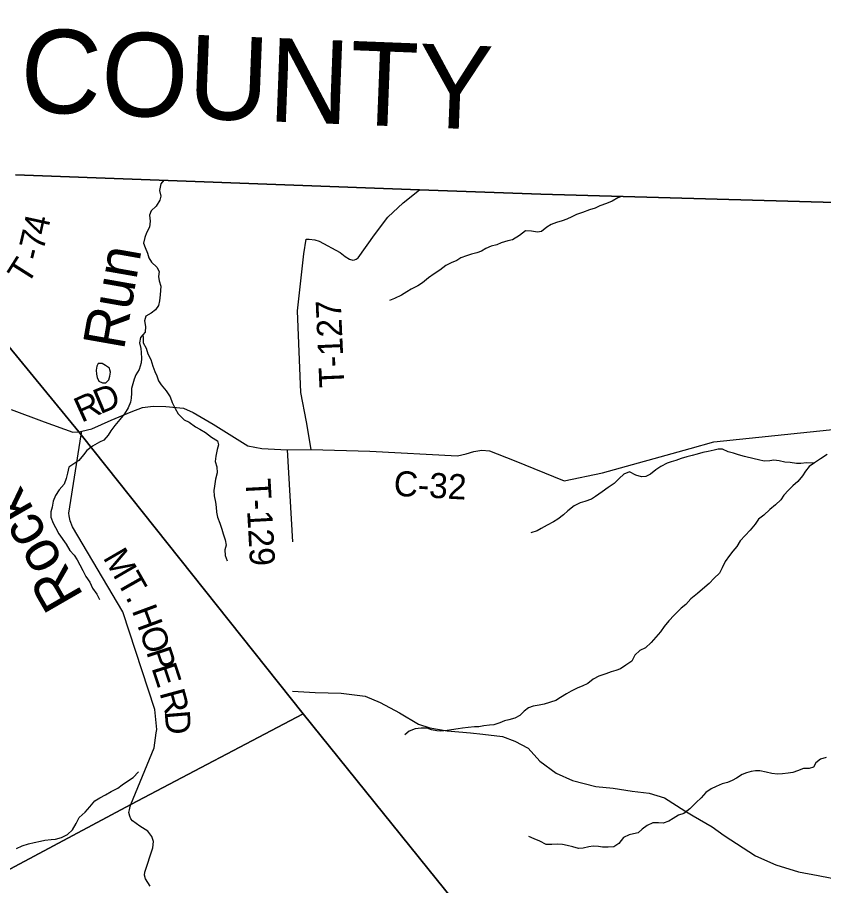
# Model space of a CAD drawing. Extents: x 1624196 to 2029251, y 146837 to 440034.
# Drawn here: x 1777616 to 1787257, y 341386 to 351773 of the extents above; entities that cross this region are included whole.
import ezdxf

# ---------------------------------------------------------------- set-up
doc = ezdxf.new("R2010")
doc.units = 0
for name, color, linetype in [('GM_X_Adjacent_County', 7, 'Continuous'), ('GM_X_Adjacent_County_Text', 7, 'Continuous'), ('GM_X_County', 7, 'Continuous'), ('GM_X_County_Road', 7, 'Continuous'), ('GM_X_County_Road_Text', 7, 'Continuous'), ('GM_X_Minor_Lake', 7, 'Continuous'), ('GM_X_Minor_River', 7, 'Continuous'), ('GM_X_Minor_River_Text', 7, 'Continuous'), ('GM_X_Township', 7, 'Continuous'), ('GM_X_Township_Road', 7, 'Continuous'), ('GM_X_Township_Road_Text', 7, 'Continuous'), ('GM_X_Township_ROW', 7, 'Continuous')]:
    doc.layers.add(name, color=color, linetype=linetype)

msp = doc.modelspace()

# ---------------------------------------------------------------- linework, layer by layer
at = {"layer": 'GM_X_Adjacent_County'}
msp.add_lwpolyline([(1826336, 348649), (1819510, 348957), (1818598, 348960), (1813935, 349079), (1813587, 349087), (1795056, 349285), (1795014, 349286), (1790774, 349462), (1789921, 349486), (1783877, 349656), (1782423, 349710), (1777594, 349890)], dxfattribs=at)
at = {"layer": 'GM_X_County'}
msp.add_lwpolyline([(1777594, 349890), (1782423, 349710), (1783877, 349656), (1789921, 349486), (1790774, 349462), (1795014, 349286), (1795056, 349285), (1813587, 349087), (1813935, 349079), (1818598, 348960), (1819510, 348957), (1826336, 348649)], dxfattribs=at)
at = {"layer": 'GM_X_County_Road'}
for points in [[(1777542, 347083), (1777938, 346934), (1778279, 346810), (1778350, 346813), (1778385, 346821)], [(1778385, 346821), (1778508, 346852), (1778739, 346954), (1778975, 347055), (1779110, 347107), (1779238, 347120), (1779391, 347118), (1779603, 347096), (1779718, 347046), (1779958, 346906), (1780370, 346648), (1780537, 346614), (1780843, 346601), (1781128, 346602), (1781831, 346584), (1782878, 346528), (1782984, 346551), (1783072, 346578), (1783170, 346597), (1783262, 346588), (1783558, 346473), (1784156, 346229), (1784612, 346325), (1785661, 346615), (1785944, 346695), (1787517, 346859)], [(1779280, 343233), (1779283, 343254), (1779258, 343492), (1778876, 344660), (1778275, 345680), (1778246, 345749), (1778235, 345810), (1778231, 345842), (1778378, 346777), (1778385, 346821)], [(1779202, 341378), (1779149, 341468), (1779137, 341510), (1779138, 341548), (1779237, 341840), (1779242, 341914), (1779223, 341974), (1779176, 342038), (1779079, 342097), (1778991, 342160), (1778972, 342185), (1778960, 342216), (1778950, 342261), (1778956, 342294), (1778965, 342332), (1778974, 342355), (1779253, 343033), (1779277, 343213), (1779280, 343233)]]:
    msp.add_lwpolyline(points, dxfattribs=at)
at = {"layer": 'GM_X_Minor_Lake'}
for points in [[(1778723, 347556), (1778717, 347575), (1778671, 347607), (1778629, 347632), (1778583, 347630), (1778565, 347599), (1778556, 347552), (1778562, 347506), (1778571, 347464)], [(1778571, 347464), (1778591, 347422), (1778633, 347399), (1778675, 347401), (1778711, 347438), (1778722, 347482), (1778730, 347528), (1778723, 347556)]]:
    msp.add_lwpolyline(points, dxfattribs=at)
at = {"layer": 'GM_X_Minor_River'}
for points in [[(1779369, 349825), (1779331, 349782), (1779316, 349702), (1779331, 349635), (1779321, 349585), (1779274, 349515), (1779215, 349460), (1779196, 349406), (1779202, 349334), (1779195, 349262), (1779160, 349194), (1779139, 349140), (1779122, 349070), (1779142, 349019), (1779171, 348951), (1779188, 348896), (1779220, 348846), (1779285, 348785), (1779311, 348734), (1779304, 348674), (1779313, 348620), (1779333, 348557), (1779326, 348505), (1779324, 348455), (1779317, 348381), (1779302, 348327), (1779267, 348273), (1779215, 348234), (1779150, 348198), (1779135, 348144), (1779149, 348076), (1779144, 348008), (1779087, 347944), (1779078, 347878), (1779091, 347812), (1779097, 347762), (1779100, 347693), (1779095, 347641), (1779072, 347561), (1779034, 347495), (1779013, 347444), (1778996, 347390), (1778982, 347332), (1778981, 347279), (1778978, 347219), (1778970, 347169), (1778939, 347101), (1778896, 347028), (1778839, 346962), (1778782, 346892), (1778735, 346825), (1778700, 346773), (1778650, 346715), (1778597, 346692), (1778514, 346645), (1778448, 346591), (1778407, 346538), (1778352, 346472), (1778289, 346433), (1778231, 346391), (1778216, 346319), (1778201, 346255), (1778176, 346187), (1778115, 346120), (1778072, 346052), (1778043, 345986), (1778031, 345912), (1778014, 345858), (1778015, 345792), (1778042, 345723), (1778070, 345671), (1778111, 345596), (1778200, 345469), (1778245, 345396), (1778295, 345341), (1778330, 345285), (1778363, 345222), (1778399, 345155), (1778436, 345085), (1778481, 345018), (1778516, 344943), (1778566, 344874), (1778597, 344810)], [(1784838, 349630), (1784797, 349612), (1784729, 349573), (1784660, 349545), (1784582, 349518), (1784523, 349489), (1784457, 349471), (1784372, 349440), (1784302, 349413), (1784245, 349388), (1784185, 349358), (1784130, 349339), (1784062, 349318), (1783998, 349294), (1783947, 349263), (1783884, 349211), (1783834, 349202), (1783764, 349213), (1783692, 349218), (1783621, 349162), (1783538, 349111), (1783480, 349100), (1783401, 349077), (1783349, 349053), (1783283, 349034), (1783216, 349007), (1783166, 348977), (1783109, 348956), (1783045, 348938), (1782985, 348921), (1782920, 348894), (1782870, 348866), (1782803, 348837), (1782739, 348806), (1782668, 348750), (1782599, 348705), (1782532, 348656), (1782459, 348598), (1782405, 348563), (1782324, 348522), (1782274, 348490), (1782207, 348449), (1782124, 348410), (1782064, 348384)], [(1779114, 347975), (1779119, 347944), (1779120, 347880), (1779156, 347815), (1779177, 347749), (1779212, 347680), (1779235, 347601), (1779261, 347537), (1779282, 347484), (1779302, 347426), (1779337, 347375), (1779396, 347304), (1779442, 347232), (1779467, 347167), (1779502, 347095), (1779539, 347028), (1779611, 346959), (1779669, 346932), (1779744, 346875), (1779796, 346846), (1779866, 346805), (1779937, 346752), (1780007, 346707), (1780022, 346657), (1780006, 346603), (1779987, 346525), (1779980, 346459), (1779999, 346394), (1780004, 346326), (1779986, 346250), (1779973, 346166), (1779964, 346114), (1779969, 346050), (1779986, 345975), (1779992, 345913), (1779997, 345853), (1780008, 345792), (1780035, 345720), (1780059, 345649), (1780076, 345593), (1780101, 345522), (1780111, 345458), (1780098, 345404), (1780099, 345334), (1780126, 345271)], [(1787144, 346441), (1787053, 346444), (1786985, 346437), (1786931, 346437), (1786857, 346446), (1786793, 346451), (1786725, 346468), (1786663, 346475), (1786612, 346467), (1786546, 346464), (1786476, 346479), (1786424, 346493), (1786312, 346519), (1786237, 346540), (1786179, 346558), (1786115, 346577), (1786049, 346606), (1785997, 346609), (1785947, 346597), (1785876, 346580), (1785812, 346567), (1785744, 346549), (1785685, 346530), (1785621, 346515), (1785555, 346497), (1785488, 346472), (1785434, 346455), (1785384, 346439), (1785311, 346398), (1785251, 346358), (1785186, 346309), (1785130, 346282), (1785080, 346278), (1785012, 346295), (1784936, 346334), (1784867, 346309), (1784813, 346255), (1784752, 346198), (1784679, 346148), (1784607, 346095), (1784530, 346040), (1784479, 346008), (1784401, 345981), (1784347, 345966), (1784272, 345930), (1784197, 345871), (1784147, 345823), (1784080, 345770), (1784026, 345739), (1783949, 345697), (1783880, 345658), (1783830, 345632), (1783754, 345607)], [(1787298, 346542), (1787220, 346490), (1787149, 346445), (1787082, 346398), (1787040, 346344), (1787003, 346288), (1786950, 346221), (1786887, 346167), (1786835, 346118), (1786782, 346058), (1786743, 346002), (1786681, 345941), (1786612, 345887), (1786543, 345818), (1786478, 345769), (1786439, 345709), (1786377, 345639), (1786318, 345574), (1786259, 345510), (1786218, 345443), (1786171, 345387), (1786131, 345335), (1786078, 345264), (1786043, 345188), (1786012, 345124), (1785949, 345063), (1785888, 344999), (1785808, 344934), (1785747, 344882), (1785670, 344817), (1785607, 344748), (1785553, 344704), (1785471, 344623), (1785405, 344555), (1785350, 344486), (1785305, 344420), (1785250, 344359), (1785195, 344293), (1785128, 344230), (1785060, 344200), (1785001, 344141), (1784962, 344073), (1784892, 344022), (1784827, 343980)], [(1784827, 343980), (1784771, 343961), (1784718, 343945), (1784652, 343920), (1784570, 343893), (1784501, 343854), (1784436, 343804), (1784368, 343771), (1784318, 343751), (1784239, 343712), (1784183, 343681), (1784110, 343638), (1784055, 343602), (1783915, 343556), (1783856, 343546), (1783784, 343531), (1783728, 343512), (1783677, 343474), (1783623, 343420), (1783564, 343389), (1783494, 343370), (1783442, 343356), (1783385, 343333), (1783313, 343308), (1783261, 343306), (1783192, 343299), (1783132, 343286), (1783080, 343284), (1783006, 343279), (1782938, 343270), (1782888, 343262), (1782807, 343249), (1782757, 343240), (1782681, 343235), (1782631, 343237), (1782569, 343250), (1782515, 343269), (1782445, 343271), (1782373, 343262), (1782302, 343233), (1782250, 343191)], [(1787286, 342918), (1787219, 342899), (1787165, 342853), (1787134, 342802), (1787082, 342786), (1787016, 342787), (1786945, 342760), (1786887, 342738), (1786834, 342733), (1786764, 342724), (1786704, 342721), (1786638, 342727), (1786570, 342744), (1786494, 342759), (1786442, 342760), (1786392, 342752), (1786335, 342735), (1786281, 342714), (1786216, 342672), (1786162, 342645), (1786107, 342619), (1786043, 342604), (1785970, 342573), (1785910, 342545), (1785847, 342498), (1785792, 342437), (1785731, 342379), (1785656, 342306), (1785584, 342250), (1785521, 342227), (1785457, 342190), (1785406, 342156), (1785336, 342133), (1785283, 342136), (1785215, 342138), (1785147, 342105), (1785088, 342060), (1785037, 342018), (1784983, 342005), (1784933, 341993), (1784862, 341962), (1784807, 341891), (1784747, 341851), (1784681, 341848), (1784614, 341847), (1784564, 341853), (1784500, 341858), (1784450, 341849), (1784380, 341833), (1784327, 341830), (1784257, 341849), (1784189, 341866), (1784135, 341877)], [(1777604, 341830), (1777674, 341861), (1777747, 341887), (1777815, 341900), (1777892, 341917), (1777944, 341930), (1778020, 341937), (1778070, 341943), (1778143, 341962), (1778215, 341999), (1778276, 342055), (1778319, 342130), (1778354, 342200), (1778427, 342264), (1778484, 342327), (1778543, 342401), (1778603, 342438), (1778670, 342473), (1778739, 342513), (1778817, 342552), (1778868, 342591), (1778931, 342635), (1779001, 342678), (1779064, 342746)], [(1784135, 341877), (1784069, 341883), (1784005, 341878), (1783939, 341877), (1783863, 341916), (1783795, 341945), (1783731, 341972)]]:
    msp.add_lwpolyline(points, dxfattribs=at)
at = {"layer": 'GM_X_Township'}
for points in [[(1777594, 349890), (1782423, 349710), (1783877, 349656), (1789921, 349486), (1790774, 349462), (1795014, 349286), (1795056, 349285), (1813587, 349087)], [(1776799, 348700), (1778350, 346813), (1778378, 346777), (1781032, 343443), (1778974, 342355), (1772145, 338706)], [(1795508, 325685), (1792128, 329660), (1790649, 331503), (1786881, 336182), (1781032, 343443), (1778378, 346777), (1778350, 346813), (1776799, 348700)], [(1772145, 338706), (1778974, 342355), (1781032, 343443), (1786881, 336182), (1790649, 331503), (1792128, 329660), (1795508, 325685)]]:
    msp.add_lwpolyline(points, dxfattribs=at)
at = {"layer": 'GM_X_Township_Road'}
for points in [[(1781128, 346602), (1781074, 346933), (1781006, 347285), (1780965, 348261), (1781041, 348945), (1781069, 349120), (1781103, 349121), (1781173, 349110), (1781226, 349094), (1781474, 348960), (1781536, 348911), (1781589, 348879), (1781629, 348868), (1781646, 348872), (1781667, 348881), (1781691, 348896), (1781886, 349173), (1782046, 349384), (1782228, 349554), (1782423, 349710)], [(1780843, 346601), (1780904, 345499)]]:
    msp.add_lwpolyline(points, dxfattribs=at)
at = {"layer": 'GM_X_Township_ROW'}
msp.add_lwpolyline([(1780905, 343711), (1781177, 343696), (1781486, 343687), (1781773, 343651), (1781954, 343576), (1782184, 343453), (1782412, 343319), (1782549, 343274), (1782754, 343237), (1783034, 343212), (1783181, 343197), (1783416, 343168), (1783563, 343115), (1783722, 343029), (1783862, 342876), (1784060, 342732), (1784253, 342644), (1784533, 342573), (1784739, 342551), (1784966, 342516), (1785171, 342492), (1785354, 342438), (1785598, 342282), (1785697, 342221), (1785923, 342088), (1786068, 341987), (1786440, 341741), (1786684, 341633), (1786957, 341552), (1787190, 341507), (1787457, 341457)], dxfattribs=at)

# ---------------------------------------------------------------- texts
at = {"layer": 'GM_X_Adjacent_County_Text'}
msp.add_text('PIKE COUNTY', height=1000, rotation=357.7714, dxfattribs=at).set_placement((1774220, 350778))
at = {"layer": 'GM_X_County_Road_Text'}
for s, rotation, p in [('D', 22.8006, (1778606, 347022)), ('R', 24.2831, (1778383, 346921)), ('C-32', 356.9143, (1782110, 346050)), ('M', 300.1999, (1778633, 345310)), ('T', 299.612, (1778796, 345029)), ('.', 296.835, (1778905, 344838)), ('H', 290.351, (1778981, 344679)), ('O', 288.1205, (1779072, 344435)), ('P', 288.1089, (1779154, 344184)), ('E', 288.107, (1779217, 343991)), ('R', 285.123, (1779314, 343694)), ('D', 274.7957, (1779376, 343470))]:
    msp.add_text(s, height=300, rotation=rotation, dxfattribs=at).set_placement(p)
at = {"layer": 'GM_X_Minor_River_Text'}
for s, rotation, p in [('Run', 80.0015, (1778889, 347783)), ('Rock', 120.0028, (1778415, 344854))]:
    msp.add_text(s, height=500, rotation=rotation, dxfattribs=at).set_placement(p)
at = {"layer": 'GM_X_Township_Road_Text'}
for s, rotation, p in [('4', 77.5989, (1777969, 349155)), ('7', 76.7393, (1777926, 348970)), ('T', 57.7161, (1777735, 348561)), ('-', 76.2112, (1777896, 348848)), ('T-127', 92.5258, (1781528, 347350)), ('T-129', 273.087, (1780343, 346248))]:
    msp.add_text(s, height=300, rotation=rotation, dxfattribs=at).set_placement(p)

doc.saveas('drawing.dxf')
